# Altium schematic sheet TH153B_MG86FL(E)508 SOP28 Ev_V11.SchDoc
size 279 x 193 mm; PageSetup: Record=PageOptions|CenterHorizontal=True|CenterVertical=True|PrintScale=1.02|XCorrection=1.00|YCorrection=1.00|PrintKind=0|BorderSize=5000000|LeftOffset=0|BottomOffset=0|Orientation=2|PaperLength=1000|PaperWidth=1000|Scale=100|PaperSource=7|PrintQuality=-4|MediaType=1|DitherType=10|PaperKind=A4 (210 x 297 mm)|PrintScaleMode=1
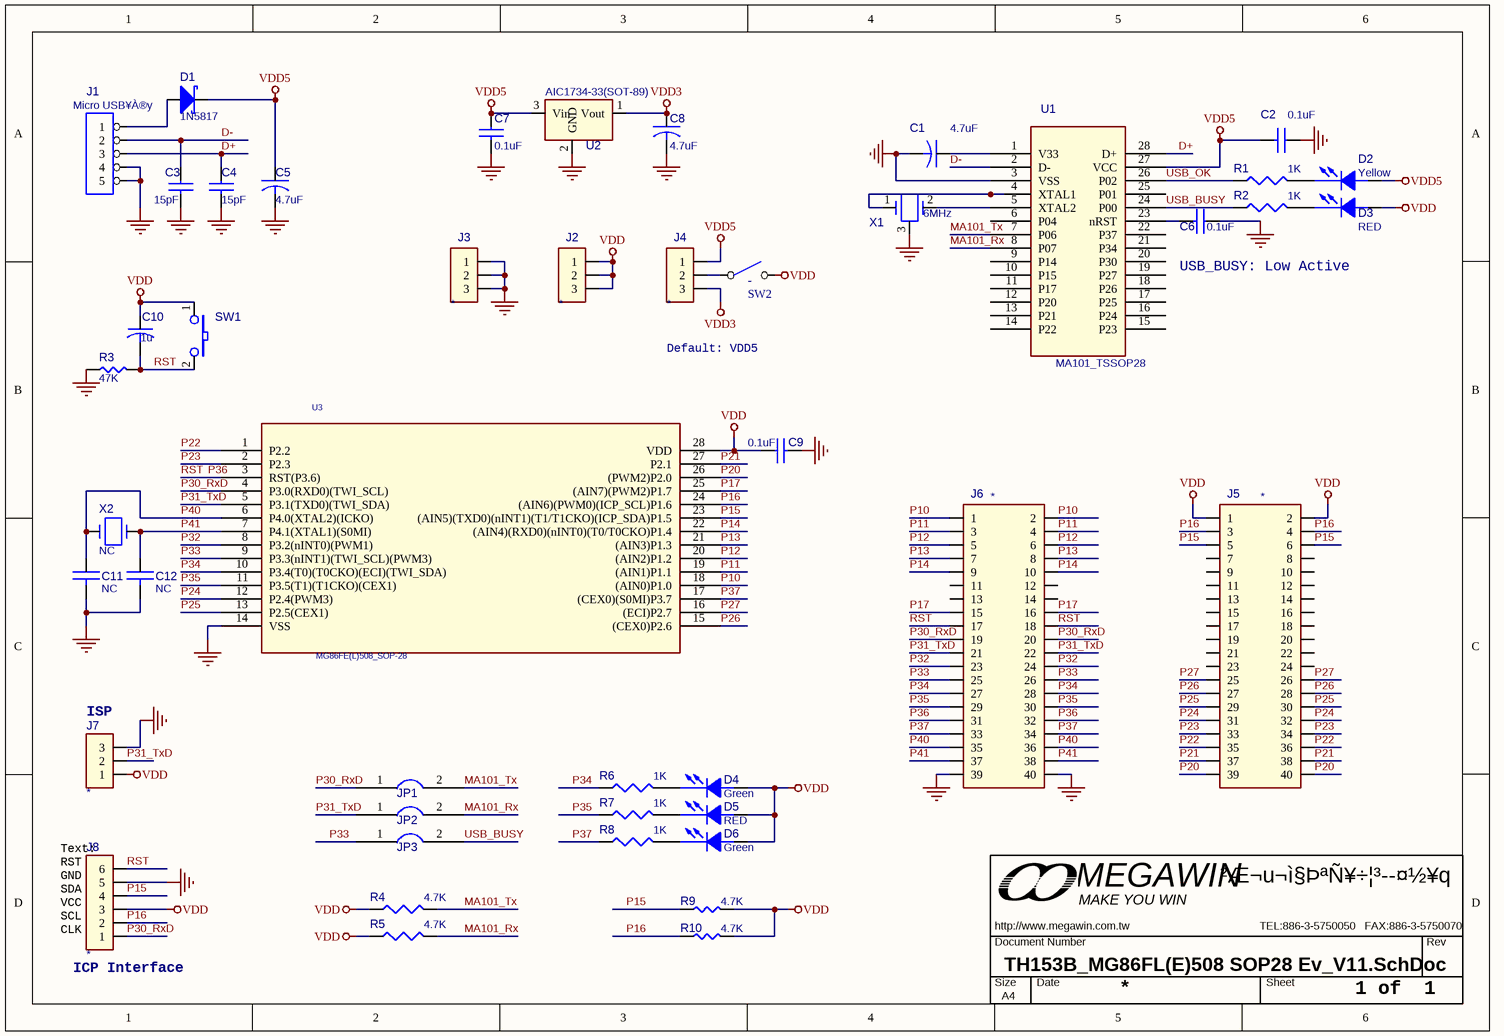
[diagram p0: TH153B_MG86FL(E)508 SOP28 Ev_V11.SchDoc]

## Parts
C1  4.7uF  [0805C]
C2  0.1uF  [0805C]
C3  15pF  [0805C]
C4  15pF  [0805C]
C5  4.7uF  [1206C]
C6  0.1uF  [0805C]
C7  0.1uF  [0805C]
C8  4.7uF  [0805C]
C9  0.1uF  [0805C]
C10  1u  [0805C]
C11  NC  [0805C]
C12  NC  [0805C]
D1  1N5817  [D5817_SMD_1]
D2  Yellow  [0805D]
D3  RED  [0805D]
D4  Green  [0805D]
D5  RED  [0805D]
D6  Green  [0805D]
J1  Micro USB¥À®y  [JACK_USB_SMD290X220P065]
J2  *  [PS3P254]
J3  *  [PS3P254]
J4  *  [JUMP3_SMD]
J5  *  [PS20X2P254]
J6  *  [PS20X2P254]
J7  *  [PS3P254f_90]
J8  *  [PS6P254F_90]
JP1  JUMPER2  [PS2P254]  (value not drawn)
JP2  JUMPER2  [PS2P254]  (value not drawn)
JP3  JUMPER2  [PS2P254]  (value not drawn)
MW1  OrgName: ²Æ¬u¬ì§ÞªÑ¥÷¦³­­¤½¥q  OrgAddr1: MEGAWIN  OrgAddr3: TEL:886-3-5750050   FAX:886-3-5750070  Page Size: A4  [MEGAWIN_T]  (hidden comment: MW-A4)  (no BOM)
R1  1K  [0805R]
R2  1K  [0805R]
R3  47K  [0805R]
R4  4.7K  [0805R]
R5  4.7K  [0805R]
R6  1K  [0805R]
R7  1K  [0805R]
R8  1K  [0805R]
R9  4.7K  [0805R]
R10  4.7K  [0805R]
SW1  SW TACT-SPST  [SW_T_2P]  (value not drawn)
SW2  -  [DIP2_SW]
U1  MA101_TSSOP28  [TSSOP28_170P065]
U2  AIC1734-33(SOT-89)  [SOT89]
U3  MG86FE(L)508_SOP-28  [SO28_300P127]
X1  6MHz  [X3P]
X2  NC  [X49U]

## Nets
GND_POWER: C1.2 C2.1 C3.2 C4.2 C5.2 C6.1 C7.2 C8.2 C9.2 C11.2 C12.2 J1.4 J1.5 J3.1 J3.2 J3.3 J6.39 J6.40 J7.3 J8.5 R3.1 U1.3(VSS) U2.2(GND) U3.14(VSS) X1.3
VDD: C9.1 C10.1(POS) D3.1(ANODE) D4.1(ANODE) D5.1(ANODE) D6.1(ANODE) J2.1 J2.2 J2.3 J5.1 J5.2 J7.1 J8.3 R4.1 R5.1 R9.2 R10.2 SW1.1 SW2.2(NO) U3.28(VDD)
VDD3: C8.1 J4.3 U2.1(Vout)
VDD5: C2.2 C5.1 C7.1 D1.2(K) D2.1(ANODE) J4.1 U1.27(VCC) U2.3(Vin)
D+: C4.1 J1.3 U1.28(D+)
D-: C3.1 J1.2 U1.2(D-)
MA101_Rx: JP2.2 R5.2 U1.8(P07)
MA101_Tx: JP1.2 R4.2 U1.7(P06)
P10: J6.1 J6.2 U3.18((AIN0)P1.0)
P11: J6.3 J6.4 U3.19((AIN1)P1.1)
P12: J6.5 J6.6 U3.20((AIN2)P1.2)
P13: J6.7 J6.8 U3.21((AIN3)P1.3)
P14: J6.9 J6.10 U3.22((AIN4)(RXD0)(nINT0)(T0/T0CKO)P1.4)
P15: J5.5 J5.6 J8.4 R9.1 U3.23((AIN5)(TXD0)(nINT1)(T1/T1CKO)(ICP_SDA)P1.5)
P16: J5.3 J5.4 J8.2 R10.1 U3.24((AIN6)(PWM0)(ICP_SCL)P1.6)
P17: J6.15 J6.16 U3.25((AIN7)(PWM2)P1.7)
P20: J5.39 J5.40 U3.26((PWM2)P2.0)
P21: J5.37 J5.38 U3.27(P2.1)
P22: J5.35 J5.36 U3.1(P2.2)
P23: J5.33 J5.34 U3.2(P2.3)
P24: J5.31 J5.32 U3.12(P2.4(PWM3))
P25: J5.29 J5.30 U3.13(P2.5(CEX1))
P26: J5.27 J5.28 U3.15((CEX0)P2.6)
P27: J5.25 J5.26 U3.16((ECI)P2.7)
P30_RxD: J6.19 J6.20 J8.1 JP1.1 U3.4(P3.0(RXD0)(TWI_SCL))
P31_TxD: J6.21 J6.22 J7.2 JP2.1 U3.5(P3.1(TXD0)(TWI_SDA))
P32: J6.23 J6.24 U3.8(P3.2(nINT0)(PWM1))
P33: J6.25 J6.26 JP3.1 U3.9(P3.3(nINT1)(TWI_SCL)(PWM3))
P34: J6.27 J6.28 R6.1 U3.10(P3.4(T0)(T0CKO)(ECI)(TWI_SDA))
P35: J6.29 J6.30 R7.1 U3.11(P3.5(T1)(T1CKO)(CEX1))
P36: C10.2(NEG) J6.17 J6.18 J6.31 J6.32 J8.6 R3.2 SW1.2 U3.3(RST(P3.6))  [also labelled RST]
P37: J6.33 J6.34 R8.1 U3.17((CEX0)(S0MI)P3.7)
P40: C11.1 J6.35 J6.36 U3.6(P4.0(XTAL2)(ICKO)) X2.1
P41: C12.1 J6.37 J6.38 U3.7(P4.1(XTAL1)(S0MI)) X2.2
USB_BUSY: JP3.2 R2.1 U1.24(P00)
USB_OK: R1.1 U1.26(P02)
NetC1_1: C1.1 U1.1(V33)
NetC6_2: C6.2 U1.23(nRST)
NetD1_1: D1.1(A) J1.1
NetD2_2: D2.2(CATHODE) R1.2
NetD3_2: D3.2(CATHODE) R2.2
NetD4_2: D4.2(CATHODE) R6.2
NetD5_2: D5.2(CATHODE) R7.2
NetD6_2: D6.2(CATHODE) R8.2
NetJ4_2: J4.2 SW2.1(COMMON)
NetU1_4: U1.4(XTAL1) X1.1
NetU1_5: U1.5(XTAL2) X1.2

Not connected (* = marked no-connect by the designer): J5 7 8 9 10 11 12 13 14 15 16 17 18 19 20 21 22 23 24; J6 11 12 13 14; U1 6(P04) 9(P14) 10(P15) 11(P17) 12(P20) 13(P21) 14(P22) 15(P23) 16(P24) 17(P25) 18(P26) 19(P27) 20(P30) 21(P34) 22(P37) 25(P01)

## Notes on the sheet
- USB_BUSY: Low Active
- Default: VDD5
- (near J7) ISP
- (near J8) Text:
  RST
  GND
  SDA
  VCC
  SCL
  CLK
- (near J8) ICP Interface
- 1 of  1

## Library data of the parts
C1 C5 C8 = CAP
C2-C4 C6 C7 C9 = CAP NP
C10 = C
C11 C12 = C NP
D1 = DIODE_ZD: Schottky Diode
D2-D6 = LED
J1 = CON5: Connector
J2-J4 J7 = CON3
J5 J6 = CON40A
J8 = CON6
R1 R2 R4-R8 = R_Dup1
R3 R9 R10 = R
SW2 = SW-2
U2 = AIC1734-33(SOT-89)_0
U3 = MG86FE(L)508_DIP-28
X1 = CRYSTAL_RC
X2 = CRYSTAL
